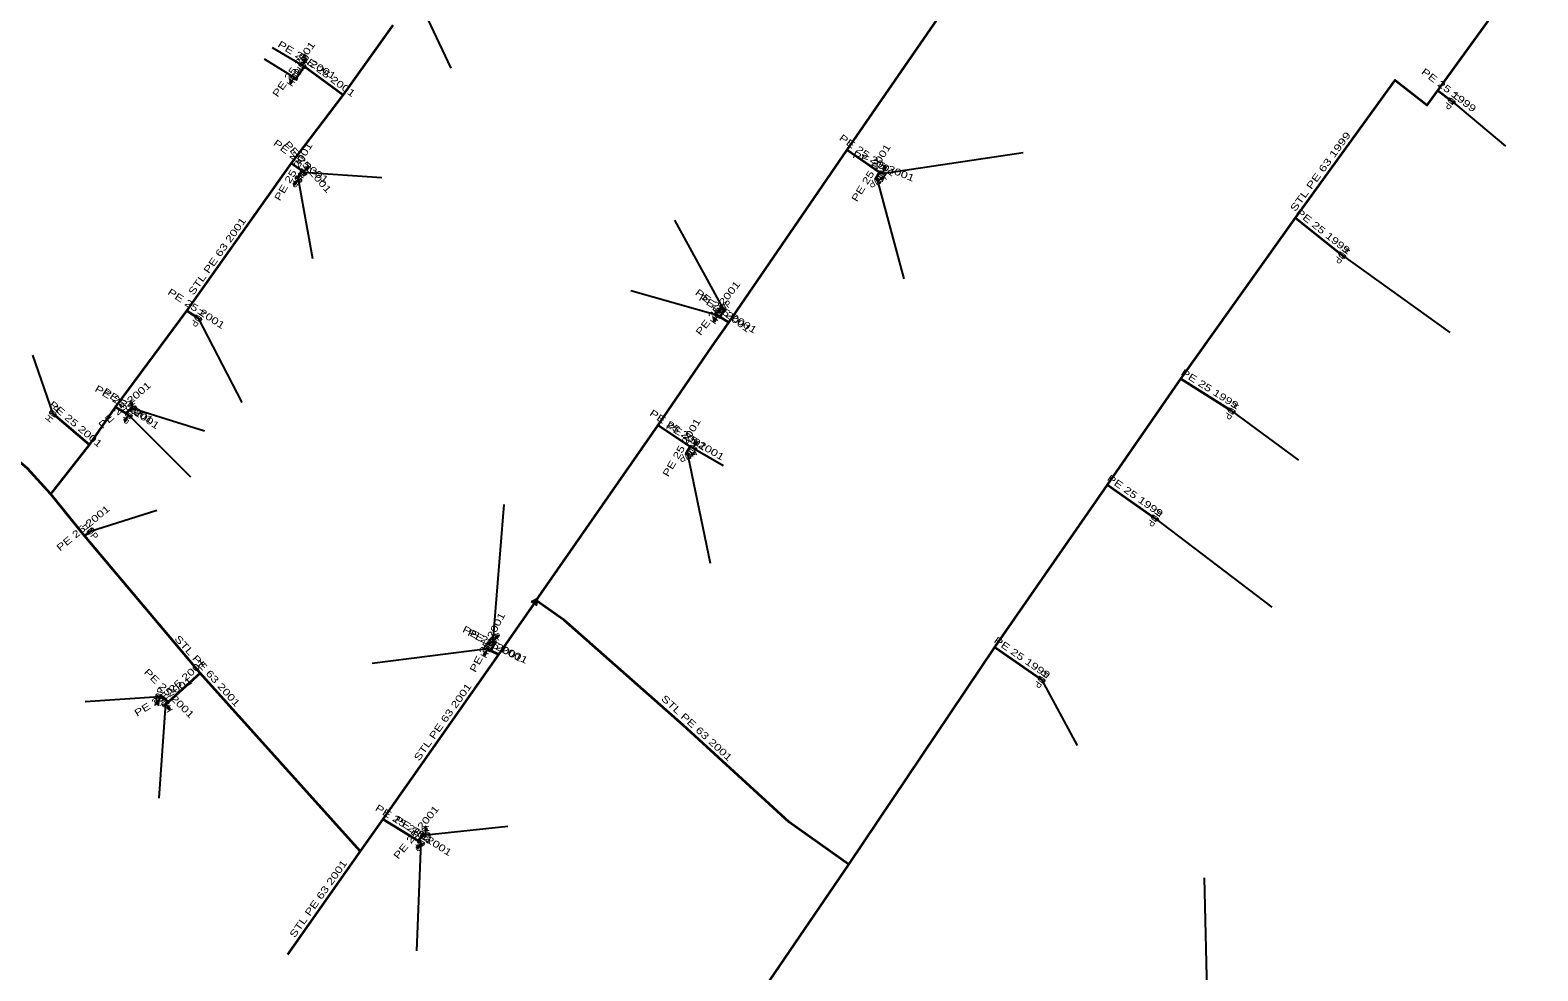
# Model space of a CAD drawing. Extents: x -737484 to -734496, y -1033882 to -1030666.
# Drawn here: x -734978.9 to -734761.8, y -1033718.3 to -1033583 of the extents above; entities that cross this region are included whole.
import ezdxf
from ezdxf.enums import TextEntityAlignment as Align

# ---------------------------------------------------------------- set-up
doc = ezdxf.new("R2010")
doc.units = 0
doc.header["$LTSCALE"] = 0.4
for name, color, linetype, lineweight in [('1', 7, 'Continuous', 13), ('22', 7, 'Continuous', 25), ('5', 7, 'Continuous', 35), ('7', 7, 'Continuous', 35)]:
    doc.layers.add(name, color=color, linetype=linetype, lineweight=lineweight)
doc.layers.add('2', color=7, linetype='Continuous')

msp = doc.modelspace()

# ---------------------------------------------------------------- linework, layer by layer
at = {"layer": '1'}
for p, q in [((-734939.74, -1033588.04), (-734939.482, -1033587.611)), ((-734939.379, -1033587.585), (-734939.199, -1033587.285)), ((-734941.313, -1033590.204), (-734941.509, -1033590.494)), ((-734940.93, -1033589.77), (-734941.209, -1033590.184)), ((-734939.6, -1033603.42), (-734939.259, -1033603.054)), ((-734939.152, -1033603.05), (-734938.914, -1033602.794)), ((-734856.38, -1033604.416), (-734856.074, -1033604.247)), ((-734856.21, -1033603.57), (-734856.022, -1033603.106)), ((-734855.925, -1033603.064), (-734855.793, -1033602.74)), ((-734940.735, -1033604.813), (-734940.946, -1033605.092)), ((-734940.33, -1033604.399), (-734940.63, -1033604.798)), ((-734856.92, -1033604.63), (-734856.482, -1033604.387)), ((-734879.684, -1033623.206), (-734879.963, -1033623.416)), ((-734879.18, -1033622.92), (-734879.579, -1033623.22)), ((-734880.29, -1033624.464), (-734880.47, -1033624.764)), ((-734879.93, -1033624.01), (-734880.187, -1033624.438)), ((-734964.236, -1033636.844), (-734964.355, -1033636.515)), ((-734965.158, -1033638.791), (-734965.364, -1033639.074)), ((-734964.76, -1033638.37), (-734965.053, -1033638.774)), ((-734964.11, -1033637.41), (-734964.281, -1033636.94)), ((-734883.48, -1033643.1), (-734883.23, -1033642.666)), ((-734883.127, -1033642.639), (-734882.952, -1033642.336)), ((-734884.22, -1033644.18), (-734883.741, -1033644.033)), ((-734883.648, -1033644.083), (-734883.313, -1033643.981)), ((-734912.26, -1033670.8), (-734911.906, -1033670.446)), ((-734911.8, -1033670.446), (-734911.552, -1033670.198)), ((-734913.421, -1033672.481), (-734913.574, -1033672.796)), ((-734913.102, -1033671.998), (-734913.321, -1033672.447)), ((-734960.542, -1033679.423), (-734960.621, -1033679.764)), ((-734960.34, -1033678.88), (-734960.452, -1033679.367)), ((-734959.46, -1033679.88), (-734959.159, -1033680.279)), ((-734959.173, -1033680.384), (-734958.963, -1033680.663)), ((-734921.91, -1033698.74), (-734921.944, -1033698.241)), ((-734921.875, -1033698.161), (-734921.899, -1033697.812)), ((-734923.056, -1033700.321), (-734923.246, -1033700.614)), ((-734922.68, -1033699.88), (-734922.952, -1033700.299))]:
    msp.add_line(p, q, dxfattribs=at)
for points in [[(-734940.27, -1033587.953), (-734940.064, -1033587.611), (-734939.413, -1033588.468), (-734939.207, -1033588.126)], [(-734939.224, -1033587.182), (-734939.353, -1033587.105), (-734939.611, -1033587.534), (-734939.482, -1033587.611)], [(-734939.224, -1033587.182), (-734939.096, -1033587.26), (-734939.353, -1033587.688), (-734939.482, -1033587.611)], [(-734939.212, -1033587.234), (-734939.148, -1033587.273), (-734939.367, -1033587.637), (-734939.431, -1033587.598)], [(-734941.489, -1033590.599), (-734941.613, -1033590.515), (-734941.333, -1033590.1), (-734941.209, -1033590.184)], [(-734941.498, -1033590.546), (-734941.56, -1033590.504), (-734941.323, -1033590.152), (-734941.26, -1033590.194)], [(-734941.489, -1033590.599), (-734941.364, -1033590.682), (-734941.085, -1033590.268), (-734941.209, -1033590.184)], [(-734941.459, -1033589.673), (-734941.247, -1033589.334), (-734940.61, -1033590.203), (-734940.398, -1033589.864)], [(-734773.74, -1033593.281), (-734773.981, -1033593.6), (-734774.538, -1033592.679), (-734774.779, -1033592.998)], [(-734939.818, -1033604.568), (-734940.075, -1033604.874), (-734940.584, -1033603.925), (-734940.841, -1033604.231)], [(-734939.12, -1033603.665), (-734939.421, -1033603.927), (-734939.776, -1033602.91), (-734940.077, -1033603.172)], [(-734938.918, -1033602.688), (-734939.027, -1033602.586), (-734939.368, -1033602.952), (-734939.259, -1033603.054)], [(-734938.918, -1033602.688), (-734938.808, -1033602.79), (-734939.149, -1033603.156), (-734939.259, -1033603.054)], [(-734938.916, -1033602.741), (-734938.862, -1033602.792), (-734939.151, -1033603.103), (-734939.206, -1033603.052)], [(-734856.502, -1033604.969), (-734856.852, -1033605.163), (-734856.987, -1033604.094), (-734857.337, -1033604.288)], [(-734855.67, -1033603.571), (-734855.82, -1033603.942), (-734856.597, -1033603.197), (-734856.747, -1033603.568)], [(-734856.045, -1033604.145), (-734856.118, -1033604.013), (-734856.555, -1033604.256), (-734856.482, -1033604.387)], [(-734856.045, -1033604.145), (-734855.972, -1033604.276), (-734856.409, -1033604.518), (-734856.482, -1033604.387)], [(-734856.06, -1033604.195), (-734856.024, -1033604.261), (-734856.396, -1033604.467), (-734856.432, -1033604.402)], [(-734855.835, -1033602.642), (-734855.974, -1033602.586), (-734856.161, -1033603.05), (-734856.022, -1033603.106)], [(-734855.835, -1033602.642), (-734855.696, -1033602.699), (-734855.883, -1033603.162), (-734856.022, -1033603.106)], [(-734855.815, -1033602.691), (-734855.745, -1033602.72), (-734855.904, -1033603.114), (-734855.974, -1033603.085)], [(-734940.931, -1033605.197), (-734941.051, -1033605.107), (-734940.75, -1033604.708), (-734940.63, -1033604.798)], [(-734940.938, -1033605.145), (-734940.998, -1033605.099), (-734940.742, -1033604.76), (-734940.682, -1033604.805)], [(-734940.931, -1033605.197), (-734940.812, -1033605.287), (-734940.511, -1033604.888), (-734940.63, -1033604.798)], [(-734789.504, -1033615.508), (-734789.756, -1033615.819), (-734790.281, -1033614.878), (-734790.533, -1033615.189)], [(-734880.451, -1033623.877), (-734880.215, -1033623.554), (-734879.642, -1033624.465), (-734879.406, -1033624.142)], [(-734879.978, -1033623.521), (-734880.068, -1033623.402), (-734879.669, -1033623.101), (-734879.579, -1033623.22)], [(-734879.97, -1033623.469), (-734880.015, -1033623.409), (-734879.676, -1033623.153), (-734879.631, -1033623.213)], [(-734879.978, -1033623.521), (-734879.888, -1033623.641), (-734879.489, -1033623.34), (-734879.579, -1033623.22)], [(-734879.64, -1033622.64), (-734879.321, -1033622.399), (-734879.038, -1033623.438), (-734878.719, -1033623.197)], [(-734954.24, -1033624.494), (-734954.458, -1033624.83), (-734955.079, -1033623.949), (-734955.297, -1033624.285)], [(-734880.445, -1033624.867), (-734880.573, -1033624.789), (-734880.316, -1033624.361), (-734880.187, -1033624.438)], [(-734880.457, -1033624.815), (-734880.521, -1033624.776), (-734880.302, -1033624.412), (-734880.238, -1033624.451)], [(-734880.445, -1033624.867), (-734880.316, -1033624.944), (-734880.058, -1033624.515), (-734880.187, -1033624.438)], [(-734964.452, -1033636.47), (-734964.592, -1033636.521), (-734964.421, -1033636.991), (-734964.281, -1033636.94)], [(-734964.452, -1033636.47), (-734964.311, -1033636.419), (-734964.14, -1033636.888), (-734964.281, -1033636.94)], [(-734964.404, -1033636.493), (-734964.333, -1033636.467), (-734964.188, -1033636.867), (-734964.258, -1033636.892)], [(-734976.161, -1033638.02), (-734975.904, -1033637.714), (-734975.395, -1033638.663), (-734975.138, -1033638.357)], [(-734965.347, -1033639.179), (-734965.469, -1033639.09), (-734965.175, -1033638.686), (-734965.053, -1033638.774)], [(-734965.355, -1033639.126), (-734965.416, -1033639.082), (-734965.166, -1033638.738), (-734965.105, -1033638.782)], [(-734965.347, -1033639.179), (-734965.226, -1033639.267), (-734964.932, -1033638.862), (-734965.053, -1033638.774)], [(-734964.232, -1033638.482), (-734964.456, -1033638.814), (-734965.061, -1033637.923), (-734965.285, -1033638.255)], [(-734963.707, -1033637.051), (-734963.57, -1033637.426), (-734964.647, -1033637.393), (-734964.51, -1033637.768)], [(-734805.419, -1033637.825), (-734805.631, -1033638.164), (-734806.268, -1033637.295), (-734806.48, -1033637.634)], [(-734882.946, -1033643.176), (-734883.146, -1033643.523), (-734883.813, -1033642.676), (-734884.013, -1033643.023)], [(-734882.98, -1033642.233), (-734883.109, -1033642.158), (-734883.359, -1033642.591), (-734883.23, -1033642.666)], [(-734882.98, -1033642.233), (-734882.85, -1033642.308), (-734883.1, -1033642.741), (-734883.23, -1033642.666)], [(-734882.966, -1033642.285), (-734882.902, -1033642.322), (-734883.114, -1033642.69), (-734883.179, -1033642.653)], [(-734883.821, -1033644.54), (-734884.18, -1033644.716), (-734884.259, -1033643.641), (-734884.618, -1033643.817)], [(-734883.263, -1033643.887), (-734883.307, -1033643.744), (-734883.785, -1033643.89), (-734883.741, -1033644.033)], [(-734883.263, -1033643.887), (-734883.219, -1033644.031), (-734883.697, -1033644.177), (-734883.741, -1033644.033)], [(-734883.289, -1033643.934), (-734883.267, -1033644.005), (-734883.673, -1033644.13), (-734883.695, -1033644.058)], [(-734816.475, -1033653.291), (-734816.705, -1033653.619), (-734817.294, -1033652.718), (-734817.524, -1033653.046)], [(-734970.007, -1033654.578), (-734969.755, -1033654.889), (-734970.784, -1033655.208), (-734970.532, -1033655.519)], [(-734906.786, -1033665.182), (-734905.967, -1033665.756), (-734905.803, -1033664.65)], [(-734906.042, -1033665.581), (-734905.931, -1033664.833), (-734906.596, -1033665.193)], [(-734906.059, -1033665.016), (-734906.406, -1033665.204), (-734906.117, -1033665.407)], [(-734912.725, -1033670.529), (-734912.41, -1033670.282), (-734912.109, -1033671.317), (-734911.794, -1033671.07)], [(-734911.552, -1033670.092), (-734911.658, -1033669.986), (-734912.012, -1033670.34), (-734911.906, -1033670.446)], [(-734911.552, -1033670.092), (-734911.446, -1033670.198), (-734911.8, -1033670.552), (-734911.906, -1033670.446)], [(-734911.553, -1033670.145), (-734911.5, -1033670.198), (-734911.801, -1033670.499), (-734911.854, -1033670.446)], [(-734913.54, -1033672.896), (-734913.675, -1033672.831), (-734913.456, -1033672.381), (-734913.321, -1033672.447)], [(-734913.634, -1033671.94), (-734913.446, -1033671.587), (-734912.751, -1033672.41), (-734912.563, -1033672.057)], [(-734913.556, -1033672.846), (-734913.624, -1033672.813), (-734913.438, -1033672.431), (-734913.37, -1033672.464)], [(-734913.54, -1033672.896), (-734913.405, -1033672.962), (-734913.186, -1033672.513), (-734913.321, -1033672.447)], [(-734832.784, -1033676.512), (-734833.014, -1033676.84), (-734833.603, -1033675.939), (-734833.833, -1033676.267)], [(-734960.87, -1033678.97), (-734960.787, -1033678.579), (-734959.892, -1033679.178), (-734959.809, -1033678.787)], [(-734960.564, -1033679.854), (-734960.711, -1033679.82), (-734960.598, -1033679.333), (-734960.452, -1033679.367)], [(-734960.592, -1033679.809), (-734960.665, -1033679.792), (-734960.569, -1033679.378), (-734960.496, -1033679.394)], [(-734960.564, -1033679.854), (-734960.418, -1033679.888), (-734960.306, -1033679.4), (-734960.452, -1033679.367)], [(-734959.785, -1033680.308), (-734959.991, -1033679.966), (-734958.928, -1033679.793), (-734959.134, -1033679.451)], [(-734958.858, -1033680.678), (-734958.738, -1033680.588), (-734959.039, -1033680.189), (-734959.159, -1033680.279)], [(-734958.858, -1033680.678), (-734958.977, -1033680.768), (-734959.278, -1033680.369), (-734959.159, -1033680.279)], [(-734958.91, -1033680.67), (-734958.97, -1033680.715), (-734959.226, -1033680.376), (-734959.166, -1033680.331)], [(-734922.151, -1033699.983), (-734922.369, -1033700.319), (-734922.99, -1033699.438), (-734923.208, -1033699.774)], [(-734921.425, -1033698.505), (-734921.397, -1033698.904), (-734922.422, -1033698.575), (-734922.394, -1033698.974)], [(-734921.979, -1033697.742), (-734922.129, -1033697.752), (-734922.094, -1033698.251), (-734921.944, -1033698.241)], [(-734921.979, -1033697.742), (-734921.83, -1033697.731), (-734921.795, -1033698.23), (-734921.944, -1033698.241)], [(-734921.94, -1033697.777), (-734921.865, -1033697.772), (-734921.835, -1033698.196), (-734921.91, -1033698.201)], [(-734923.224, -1033700.718), (-734923.35, -1033700.636), (-734923.078, -1033700.217), (-734922.952, -1033700.299)], [(-734923.234, -1033700.666), (-734923.297, -1033700.625), (-734923.066, -1033700.269), (-734923.003, -1033700.31)], [(-734923.224, -1033700.718), (-734923.098, -1033700.8), (-734922.826, -1033700.381), (-734922.952, -1033700.299)]]:
    msp.add_lwpolyline(points, close=True, dxfattribs=at)
at = {"layer": '22'}
for p, q in [((-734922.55, -1033579.599), (-734918.344, -1033588.451)), ((-734939.739, -1033588.04), (-734944.036, -1033585.484)), ((-734940.929, -1033589.769), (-734945.187, -1033587.147)), ((-734774.26, -1033593.14), (-734766.486, -1033599.656)), ((-734856.209, -1033603.57), (-734835.936, -1033600.565)), ((-734939.599, -1033603.419), (-734928.318, -1033604.154)), ((-734940.33, -1033604.4), (-734938.291, -1033615.825)), ((-734856.92, -1033604.629), (-734853.128, -1033618.767)), ((-734879.18, -1033622.919), (-734886.088, -1033610.308)), ((-734790.019, -1033615.349), (-734774.515, -1033626.493)), ((-734879.929, -1033624.01), (-734892.454, -1033620.494)), ((-734954.769, -1033624.39), (-734948.458, -1033636.521)), ((-734975.65, -1033638.189), (-734978.572, -1033629.711)), ((-734964.759, -1033638.369), (-734955.856, -1033647.227)), ((-734964.109, -1033637.41), (-734953.845, -1033640.644)), ((-734805.95, -1033637.73), (-734796.305, -1033644.843)), ((-734883.48, -1033643.1), (-734879.165, -1033645.626)), ((-734884.22, -1033644.179), (-734881.005, -1033659.687)), ((-734970.27, -1033655.049), (-734960.725, -1033652.025)), ((-734912.26, -1033670.8), (-734910.676, -1033651.21)), ((-734817, -1033653.169), (-734800.156, -1033665.986)), ((-734913.099, -1033671.999), (-734929.704, -1033674.111)), ((-734833.309, -1033676.39), (-734828.189, -1033685.902)), ((-734960.34, -1033678.879), (-734971.036, -1033679.597)), ((-734959.46, -1033679.88), (-734960.428, -1033693.496)), ((-734921.91, -1033698.74), (-734910.136, -1033697.52)), ((-734922.68, -1033699.879), (-734923.304, -1033715.442)), ((-734809.33, -1033727.72), (-734809.839, -1033704.94))]:
    msp.add_line(p, q, dxfattribs=at)
at = {"layer": '5'}
msp.add_line((-734931.4, -1033701.1), (-734941.88, -1033715.98), dxfattribs=at)
for points in [[(-734906.09, -1033665.06), (-734888.5, -1033639.81), (-734880.72, -1033628.44), (-734878.34, -1033625.02), (-734861.29, -1033600.17), (-734846.09, -1033578.13), (-734833.74, -1033559.94), (-734831.24, -1033556.38), (-734822.28, -1033543.88), (-734807.45, -1033522.2), (-734804.35, -1033518.03), (-734790.66, -1033497.56), (-734781.96, -1033485.26), (-734777.54, -1033478.09), (-734765.66, -1033461.1), (-734757.47, -1033448.23), (-734746.38, -1033431.46), (-734738.04, -1033419.32), (-734736.48, -1033416), (-734735.83, -1033412.08), (-734737.89, -1033406.38), (-734742.16, -1033400.46), (-734751.3, -1033390.22), (-734751.59, -1033389.68)], [(-734975.96, -1033649.73), (-734979.32, -1033646.03), (-734992.6, -1033634.72), (-734993.41, -1033634.04), (-735000, -1033628.33), (-735005.38, -1033623.67), (-735010.2, -1033619.02), (-735022.51, -1033607.11), (-735028.53, -1033600.95), (-735033.22, -1033595.96), (-735044.58, -1033582.99), (-735050.8, -1033575.47), (-735058.43, -1033565.92), (-735069.17, -1033552.53), (-735072.33, -1033548.15), (-735079.7, -1033538.4), (-735088.3, -1033526.83), (-735092.52, -1033520.93), (-735101.55, -1033507.83), (-735102.19, -1033506.8), (-735114.06, -1033488.95), (-735115.28, -1033487.08)], [(-734861.07, -1033703.01), (-734840.02, -1033671.76), (-734823.79, -1033648.39), (-734813.26, -1033633.12), (-734796.75, -1033609.99), (-734782.37, -1033590.16), (-734777.78, -1033593.76), (-734776.25, -1033591.63), (-734765.24, -1033576.42), (-734751.48, -1033556.88), (-734737.9, -1033537.34), (-734726.95, -1033521.34), (-734721.39, -1033513.86)], [(-734975.96, -1033649.73), (-734970.39, -1033642.64), (-734966.67, -1033637.22), (-734956.36, -1033623.36), (-734942.15, -1033603.26), (-734941.29, -1033602.08), (-734933.89, -1033592.31), (-734926.67, -1033582.24)], [(-734931.4, -1033701.1), (-734954.48, -1033675.5), (-734971.11, -1033655.74), (-734975.96, -1033649.73)], [(-734906.09, -1033665.06), (-734911.49, -1033672.81), (-734928.15, -1033696.49), (-734931.4, -1033701.1)], [(-734861.07, -1033703.01), (-734869.65, -1033696.96), (-734884.89, -1033682.96), (-734902.07, -1033667.87), (-734906.09, -1033665.06)], [(-734941.67, -1033817.87), (-734936.52, -1033810.71), (-734920.97, -1033785.5), (-734895.38, -1033750.81), (-734872.39, -1033719.63), (-734861.07, -1033703.01)]]:
    msp.add_lwpolyline(points, dxfattribs=at)
at = {"layer": '7'}
for p, q in [((-734939.47, -1033588.2), (-734939.739, -1033588.04)), ((-734933.89, -1033592.31), (-734939.47, -1033588.2)), ((-734776.25, -1033591.63), (-734774.26, -1033593.14)), ((-734941.29, -1033602.08), (-734939.81, -1033603.18)), ((-734861.29, -1033600.17), (-734856.63, -1033603.4)), ((-734939.81, -1033603.18), (-734939.599, -1033603.419)), ((-734856.63, -1033603.4), (-734856.209, -1033603.57)), ((-734796.75, -1033609.99), (-734790.019, -1033615.349)), ((-734956.36, -1033623.36), (-734954.769, -1033624.39)), ((-734879.63, -1033624.23), (-734879.929, -1033624.01)), ((-734878.34, -1033625.02), (-734879.63, -1033624.23)), ((-734813.26, -1033633.12), (-734805.95, -1033637.73)), ((-734970.39, -1033642.64), (-734975.65, -1033638.189)), ((-734888.5, -1033639.81), (-734883.89, -1033642.86)), ((-734883.89, -1033642.86), (-734883.48, -1033643.1)), ((-734823.79, -1033648.39), (-734817, -1033653.169)), ((-734971.11, -1033655.74), (-734970.27, -1033655.049)), ((-734912.6, -1033672.26), (-734913.099, -1033671.999)), ((-734911.49, -1033672.81), (-734912.6, -1033672.26)), ((-734840.02, -1033671.76), (-734833.309, -1033676.39)), ((-734954.48, -1033675.5), (-734959.08, -1033679.65)), ((-734959.08, -1033679.65), (-734959.46, -1033679.88)), ((-734928.15, -1033696.49), (-734923.07, -1033699.63)), ((-734923.07, -1033699.63), (-734922.68, -1033699.879))]:
    msp.add_line(p, q, dxfattribs=at)
for points in [[(-734939.47, -1033588.2), (-734940.7, -1033589.91), (-734940.929, -1033589.769)], [(-734939.81, -1033603.18), (-734940.46, -1033604.29), (-734940.33, -1033604.4)], [(-734856.63, -1033603.4), (-734857.14, -1033604.23), (-734856.92, -1033604.629)], [(-734879.63, -1033624.23), (-734878.9, -1033623.29), (-734879.18, -1033622.919)], [(-734966.67, -1033637.22), (-734965.16, -1033638.1), (-734964.759, -1033638.369)], [(-734965.16, -1033638.1), (-734964.55, -1033637.57), (-734964.109, -1033637.41)], [(-734883.89, -1033642.86), (-734884.42, -1033643.77), (-734884.22, -1033644.179)], [(-734912.6, -1033672.26), (-734912.01, -1033671.12), (-734912.26, -1033670.8)], [(-734959.08, -1033679.65), (-734959.73, -1033679.01), (-734960.34, -1033678.879)], [(-734923.07, -1033699.63), (-734922.37, -1033698.77), (-734921.91, -1033698.74)]]:
    msp.add_lwpolyline(points, dxfattribs=at)

# ---------------------------------------------------------------- texts
at = {"layer": '2', "width": 0.95}
for rotation, p in [(59, (-734939.3098, -1033588.297)), (58, (-734940.5047, -1033590.0335)), (233, (-734774.6585, -1033592.8386)), (230, (-734940.7126, -1033604.0781)), (221, (-734939.9265, -1033603.0416)), (209, (-734857.1621, -1033604.1911)), (248, (-734856.672, -1033603.3822)), (231, (-734790.4068, -1033615.0338)), (237, (-734955.1879, -1033624.1172)), (54, (-734879.524, -1033624.3034)), (37, (-734878.8784, -1033623.3175)), (290, (-734964.5783, -1033637.5805)), (238, (-734806.3733, -1033637.4645)), (50, (-734975.2664, -1033638.5099)), (236, (-734965.1729, -1033638.0889)), (206, (-734884.4383, -1033643.7295)), (240, (-734883.9121, -1033642.8495)), (235, (-734817.4089, -1033652.8817)), (309, (-734970.6582, -1033655.3628)), (62, (-734912.657, -1033672.2332)), (38, (-734911.9513, -1033671.193)), (235, (-734833.7179, -1033676.1027)), (78, (-734959.8502, -1033678.9825)), (121, (-734959.0312, -1033679.622)), (274, (-734922.4084, -1033698.7746)), (237, (-734923.0989, -1033699.6062))]:
    msp.add_text('HUP', height=1, rotation=rotation, dxfattribs=at).set_placement(p, align=Align.CENTER)
at = {"layer": '5'}
for s, rotation, width, p in [('STL PE 63 1999', 54.052, 1.4, (-734792.7421, -1033603.611)), ('STL PE 63 2001', 54.741, 1.35, (-734951.6129, -1033615.7796)), ('STL PE 63 2001', 312.037, 1.35, (-734953.8006, -1033675.5052)), ('STL PE 63 2001', 54.872, 1.35, (-734919.1334, -1033682.8057)), ('STL PE 63 2001', 317.428, 1.35, (-734883.2913, -1033683.7492)), ('STL PE 63 2001', 54.843, 1.35, (-734937.0488, -1033708.2519))]:
    msp.add_text(s, height=1, rotation=rotation, dxfattribs=dict(at, width=width)).set_placement(p, align=Align.CENTER)
at = {"layer": '7', "width": 1.35}
for s, rotation, p in [('PE 25 2001', 329.256, (-734939.3486, -1033587.6899)), ('PE 25 2001', 54.273, (-734940.5691, -1033588.8715)), ('PE 25 2001', 323.626, (-734936.383, -1033589.8517)), ('PE 25 1999', 322.809, (-734774.9522, -1033591.9857)), ('PE 25 2001', 323.379, (-734940.2508, -1033602.2284)), ('PE 25 2001', 59.647, (-734940.6088, -1033603.5552)), ('PE 25 2001', 311.44, (-734939.3296, -1033602.9686)), ('PE 25 2001', 325.273, (-734858.6748, -1033601.3737)), ('PE 25 2001', 58.431, (-734857.43, -1033603.7468)), ('PE 25 2001', 338.011, (-734856.2317, -1033603.0209)), ('PE 25 1999', 321.474, (-734793.0724, -1033612.2783)), ('PE 25 2001', 52.167, (-734879.5173, -1033623.2692)), ('PE 25 2001', 327.081, (-734955.2922, -1033623.4549)), ('PE 25 2001', 323.655, (-734879.4823, -1033623.717)), ('PE 25 2001', 328.517, (-734878.7231, -1033624.198)), ('PE 25 1999', 327.763, (-734809.3377, -1033635.002)), ('PE 25 2001', 329.767, (-734965.6628, -1033637.228)), ('PE 25 2001', 40.986, (-734965.0059, -1033637.3028)), ('PE 25 2001', 326.145, (-734964.6805, -1033637.8182)), ('PE 25 2001', 319.762, (-734972.6965, -1033640.0328)), ('PE 25 2001', 326.511, (-734885.9189, -1033640.9172)), ('PE 25 2001', 59.783, (-734884.7014, -1033643.2596)), ('PE 25 2001', 329.657, (-734883.4321, -1033642.5474)), ('PE 25 1999', 324.861, (-734820.1068, -1033650.37)), ('PE 25 2001', 39.441, (-734971.0066, -1033655.0077)), ('PE 25 2001', 62.636, (-734912.6552, -1033671.2793)), ('PE 25 2001', 332.388, (-734912.6172, -1033671.6857)), ('PE 25 2001', 333.642, (-734911.8225, -1033672.0867)), ('PE 25 1999', 325.398, (-734836.3799, -1033673.6632)), ('PE 25 2001', 42.056, (-734957.1144, -1033677.203)), ('PE 25 2001', 315.444, (-734959.2763, -1033678.754)), ('PE 25 2001', 31.185, (-734959.5284, -1033679.337)), ('PE 25 2001', 328.279, (-734925.3464, -1033697.6336)), ('PE 25 2001', 50.856, (-734922.9617, -1033698.7051)), ('PE 25 2001', 327.443, (-734922.6056, -1033699.3332))]:
    msp.add_text(s, height=1, rotation=rotation, dxfattribs=at).set_placement(p, align=Align.CENTER)

doc.saveas('drawing.dxf')
